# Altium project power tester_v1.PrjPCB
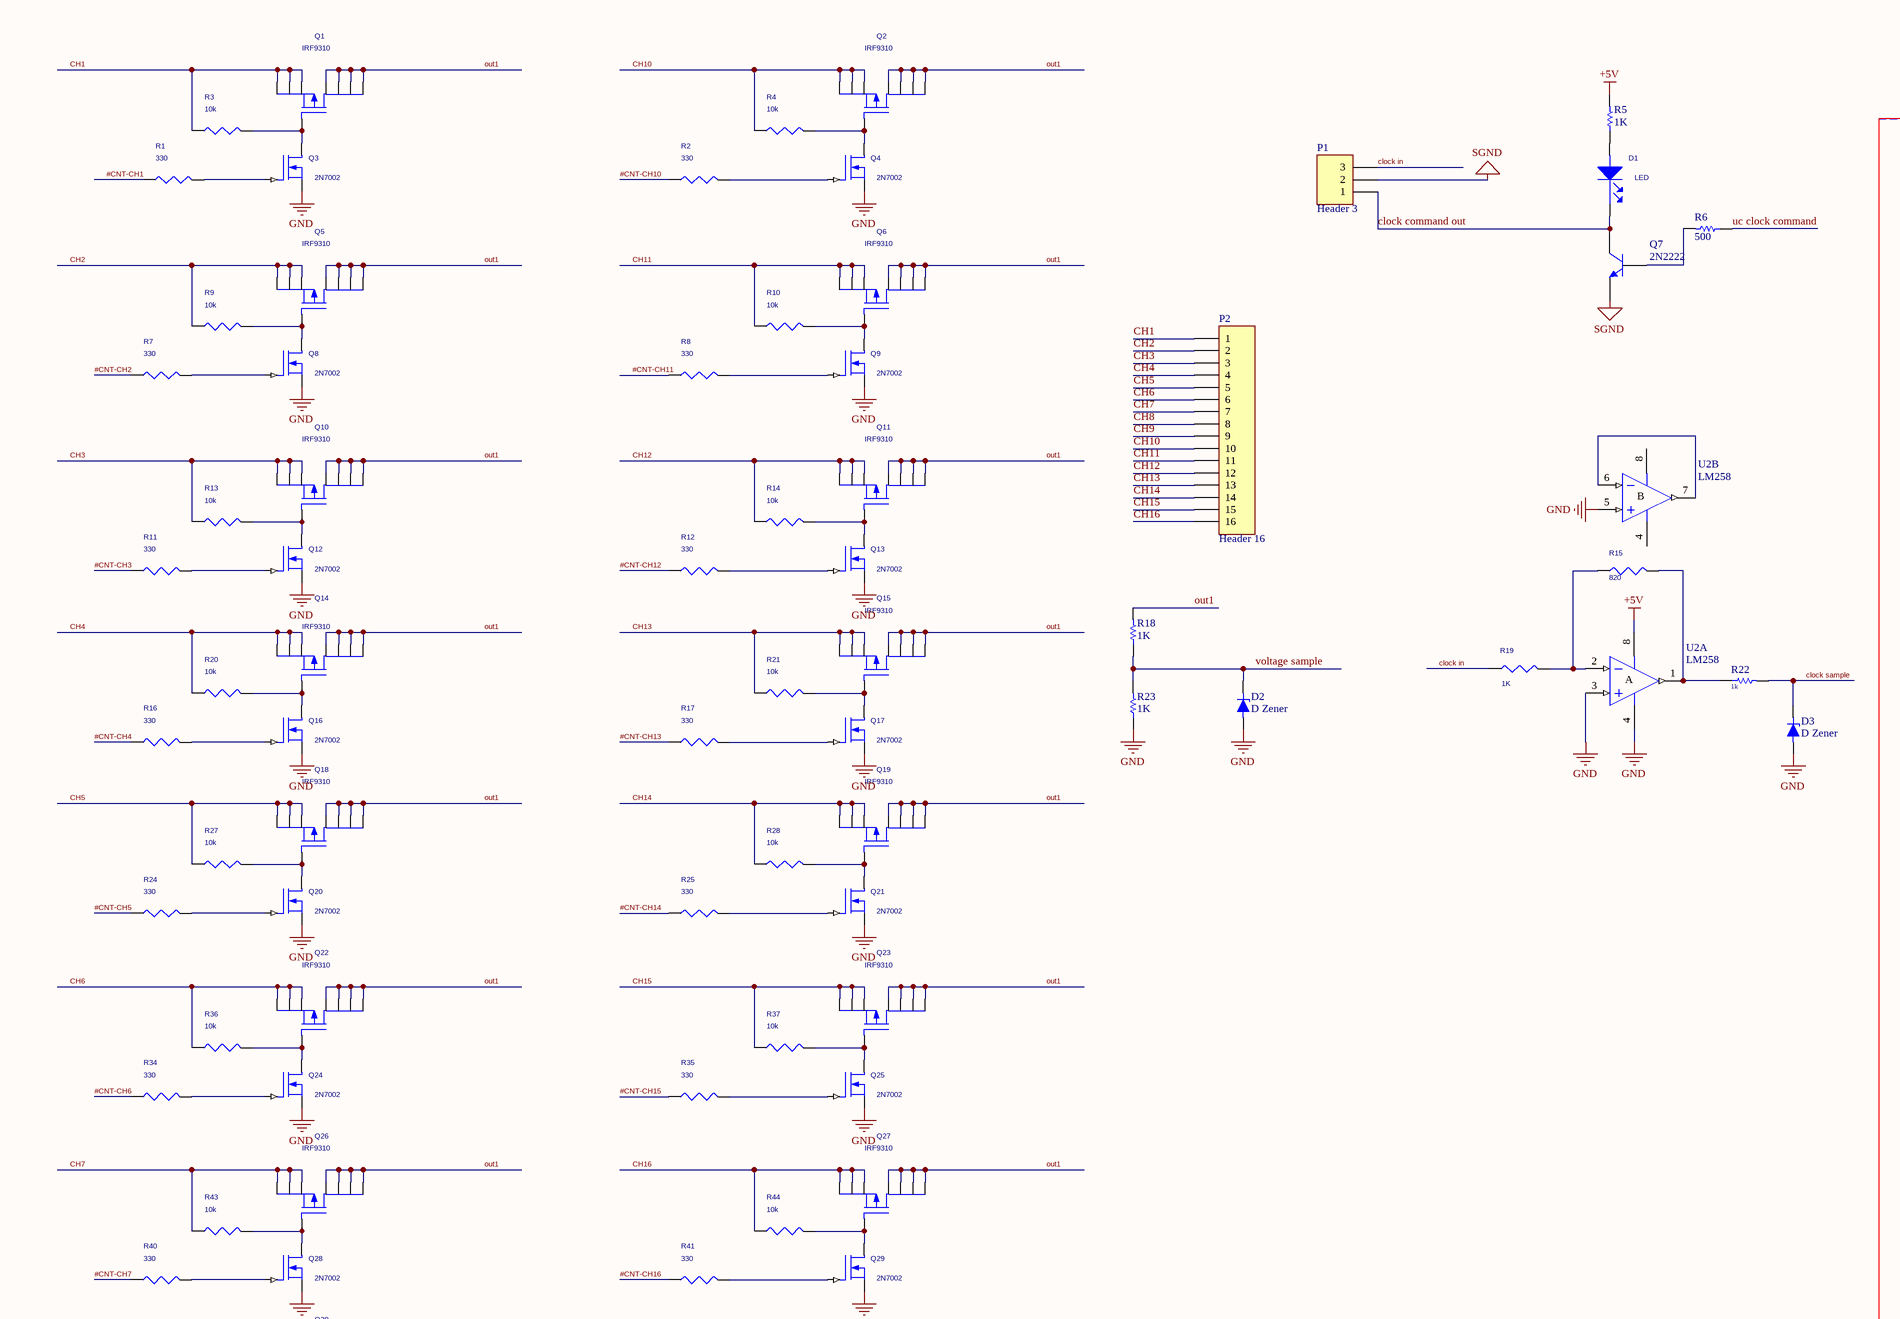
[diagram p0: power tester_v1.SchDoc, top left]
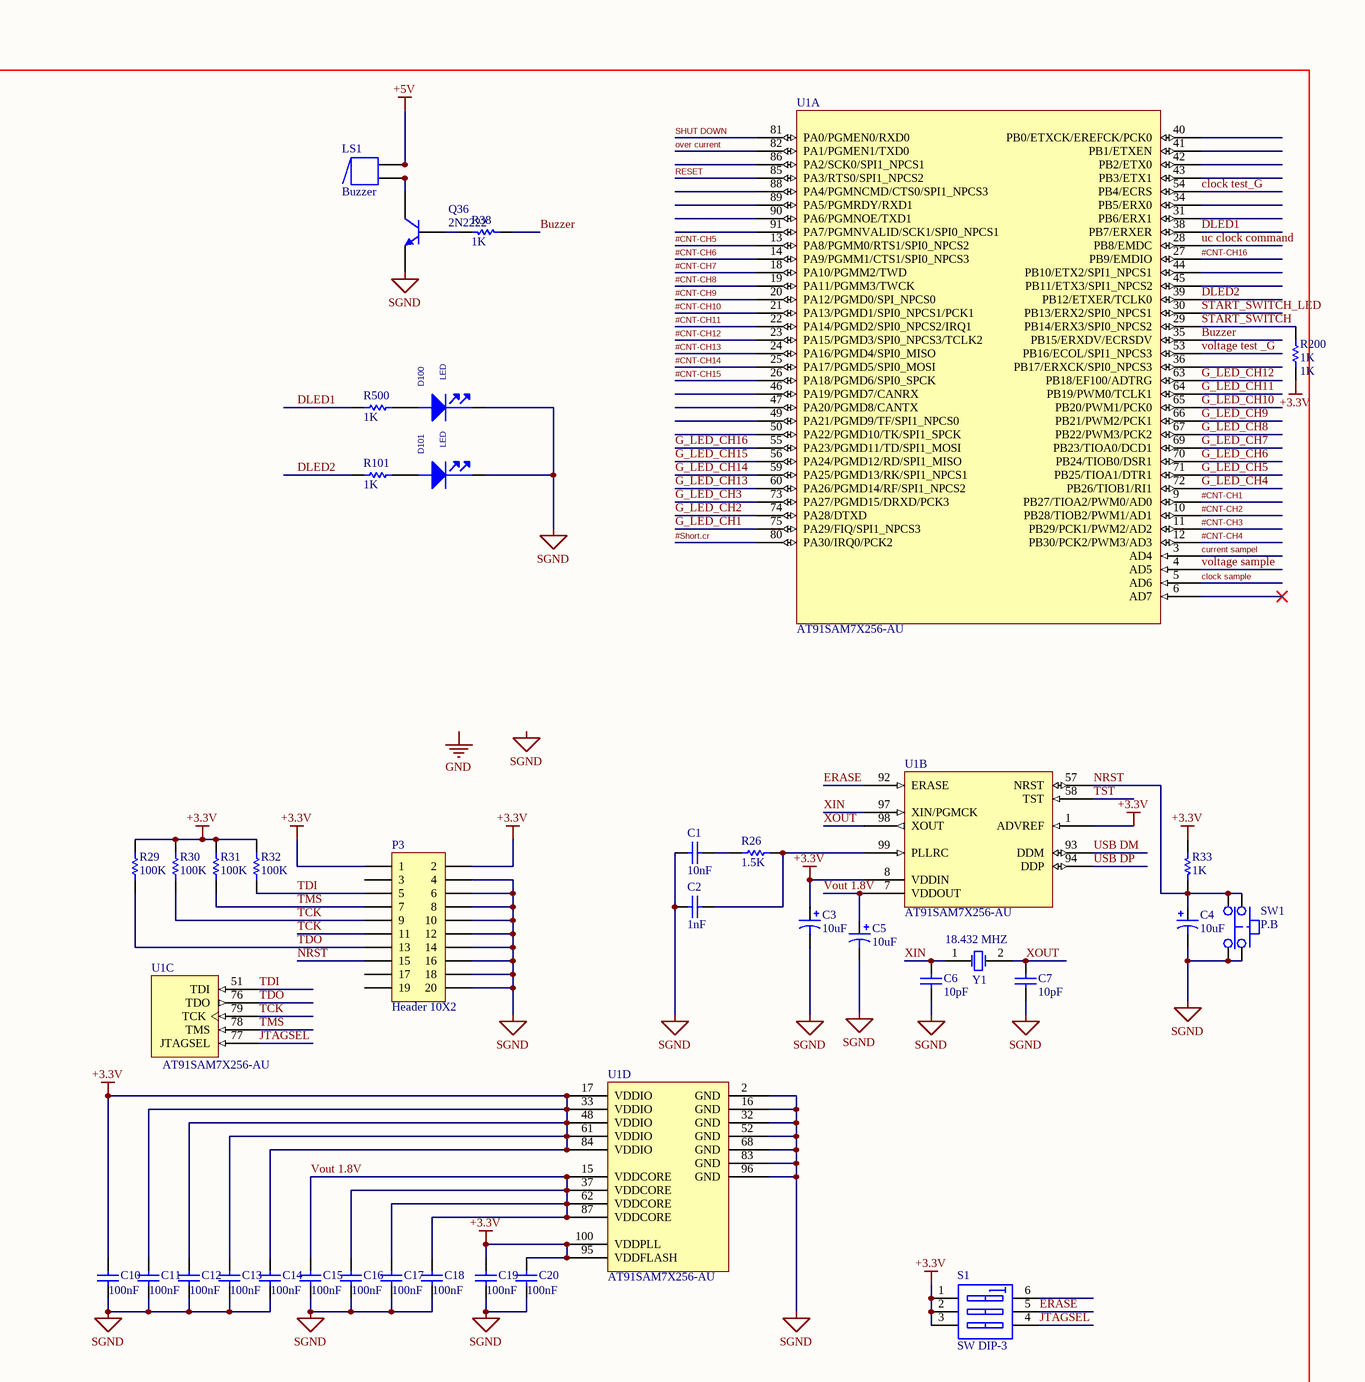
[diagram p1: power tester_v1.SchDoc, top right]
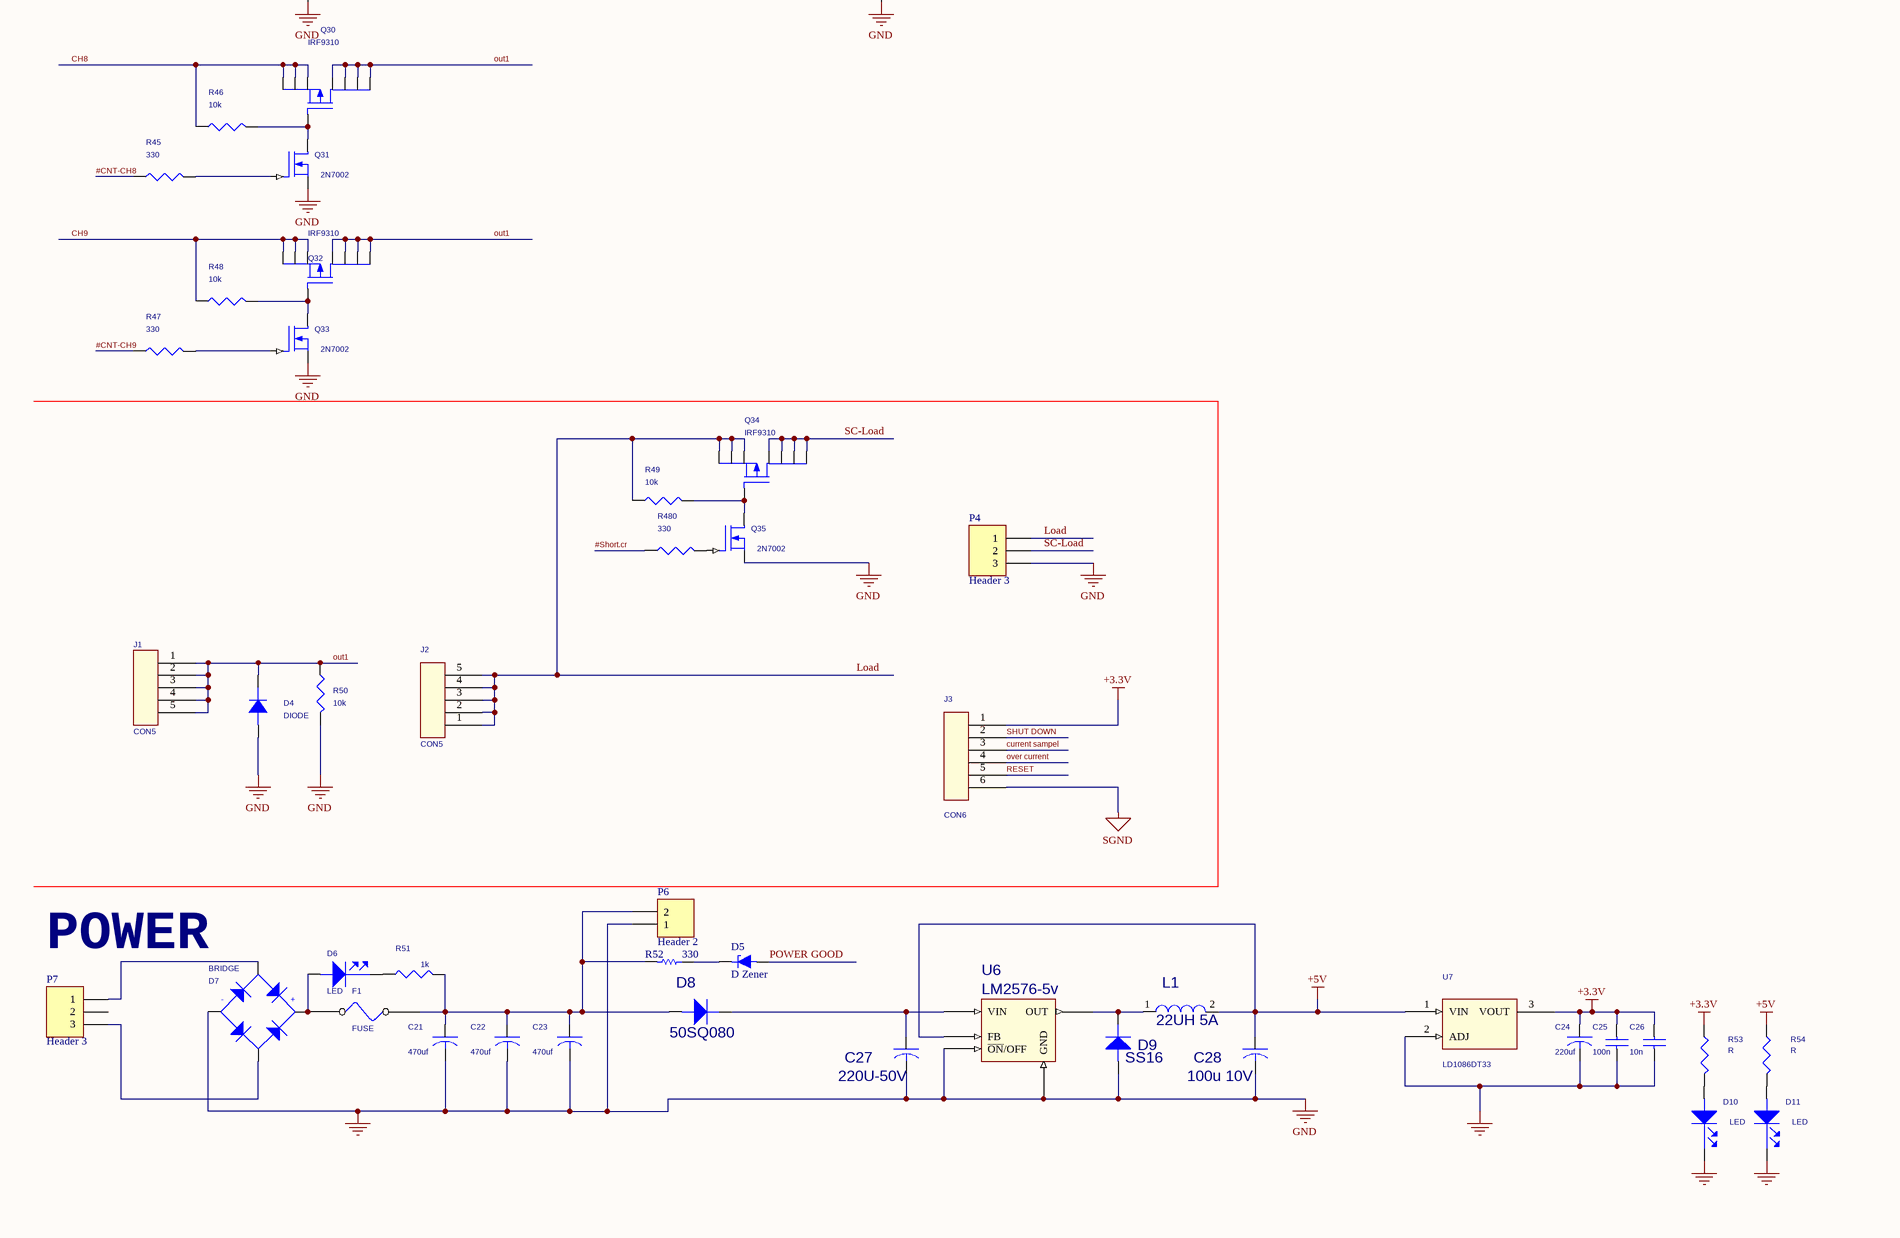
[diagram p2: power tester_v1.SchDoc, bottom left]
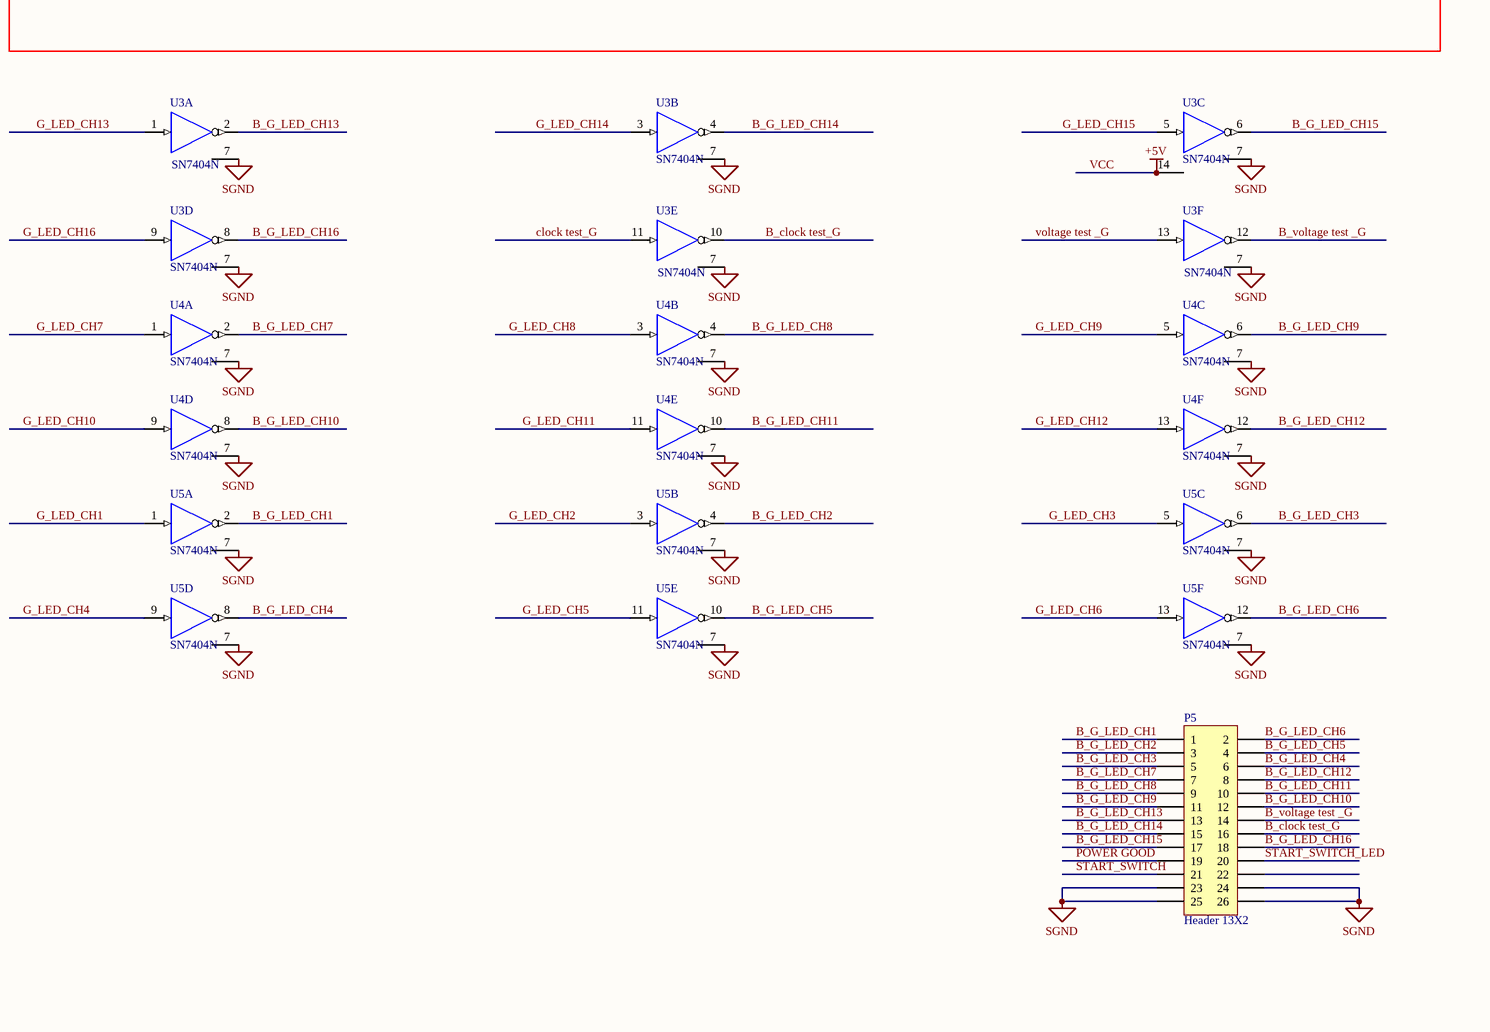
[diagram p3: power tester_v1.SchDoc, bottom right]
1 sheet, 154 parts. Net scope: global (net labels, ports and power ports of the same name join across sheets).
Board file: power tester_v1.PcbDoc

## Sheet power tester_v1.SchDoc
size 660 x 513 mm

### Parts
C1  10nF  [0603BIG]
C2  1nF  [0603BIG]
C3  10uF  [0603BIG]
C4  10uF  [0603BIG]
C5  10uF  [0603BIG]
C6  10pF  [0603BIG]
C7  10pF  [0603BIG]
C10  100nF  [0603BIG]
C11  100nF  [0603BIG]
C12  100nF  [0603BIG]
C13  100nF  [0603BIG]
C14  100nF  [0603BIG]
C15  100nF  [0603BIG]
C16  100nF  [0603BIG]
C17  100nF  [0603BIG]
C18  100nF  [0603BIG]
C19  100nF  [0603BIG]
C20  100nF  [0603BIG]
C21  470uf  [CAP-SMD-HV2]
C22  470uf  [CAP-SMD-HV2]
C23  470uf  [CAP-SMD-HV2]
C24  220uf  [1210-C]
C25  100n  [0603big]
C26  10n  [0603big]
C27  220U-50V  [CAP-SMD-HV2]
C28  100u 10V  [CAP_TANTAL_B]
D1  LED  [0805-d1]
D2  D Zener  [8-1206]
D3  D Zener  [8-1206]
D4  DIODE  [ss14]
D5  D Zener  [8-1206]
D6  LED  [0805-2D]
D7  BRIDGE  [BRG5A]
D8  50SQ080  [SS14]
D9  SS16  [SS14]
D10  LED  [0805-D1]
D11  LED  [0805-d1]
D100  LED  [0805-d1]
D101  LED  [0805-d1]
F1  FUSE  [8-1206]
J1  CON5  [SIP5]
J2  CON5  [SIP5]
J3  CON6  [SIP6]
L1  22UH 5A  [self smd]
LS1  Buzzer  [Buzzer]
P1  Header 3  [mokhaberati3PIN]
P2  Header 16  [wire_connector]
P3  Header 10X2  [IDC20]
P4  Header 3  [PHONIX 3]
P5  Header 13X2  [918526x904]
P6  Header 2  [mokhaberati]
P7  Header 3  [SIP3-155-la]
Q1  IRF9310  [so-8]
Q2  IRF9310  [so-8]
Q3  2N7002  [SOT-23]
Q4  2N7002  [SOT-23]
Q5  IRF9310  [so-8]
Q6  IRF9310  [so-8]
Q7  2N2222  [SOT23_M]
Q8  2N7002  [SOT-23]
Q9  2N7002  [SOT-23]
Q10  IRF9310  [so-8]
Q11  IRF9310  [so-8]
Q12  2N7002  [SOT-23]
Q13  2N7002  [SOT-23]
Q14  IRF9310  [so-8]
Q15  IRF9310  [so-8]
Q16  2N7002  [SOT-23]
Q17  2N7002  [SOT-23]
Q18  IRF9310  [so-8]
Q19  IRF9310  [so-8]
Q20  2N7002  [SOT-23]
Q21  2N7002  [SOT-23]
Q22  IRF9310  [so-8]
Q23  IRF9310  [so-8]
Q24  2N7002  [SOT-23]
Q25  2N7002  [SOT-23]
Q26  IRF9310  [so-8]
Q27  IRF9310  [so-8]
Q28  2N7002  [SOT-23]
Q29  2N7002  [SOT-23]
Q30  IRF9310  [so-8]
Q31  2N7002  [SOT-23]
Q32  IRF9310  [so-8]
Q33  2N7002  [SOT-23]
Q34  IRF9310  [so-8]
Q35  2N7002  [SOT-23]
Q36  2N2222  [SOT23_M]
R1  330  [0603BIG]
R2  330  [0603BIG]
R3  10k  [0603BIG]
R4  10k  [0603BIG]
R5  1K  [0603BIG]
R6  500  [0603BIG]
R7  330  [0603BIG]
R8  330  [0603BIG]
R9  10k  [0603BIG]
R10  10k  [0603BIG]
R11  330  [0603BIG]
R12  330  [0603BIG]
R13  10k  [0603BIG]
R14  10k  [0603BIG]
R15  820  [0603BIG]
R16  330  [0603BIG]
R17  330  [0603BIG]
R18  1K  [0603BIG]
R19  1K  [0603BIG]
R20  10k  [0603BIG]
R21  10k  [0603BIG]
R22  1k  [0603big]
R23  1K  [0603BIG]
R24  330  [0603BIG]
R25  330  [0603BIG]
R26  1.5K  [0603BIG]
R27  10k  [0603BIG]
R28  10k  [0603BIG]
R29  100K  [0603BIG]
R30  100K  [0603BIG]
R31  100K  [0603BIG]
R32  100K  [0603BIG]
R33  1K  [0603BIG]
R34  330  [0603BIG]
R35  330  [0603BIG]
R36  10k  [0603BIG]
R37  10k  [0603BIG]
R38  1K  [0603BIG]
R40  330  [0603BIG]
R41  330  [0603BIG]
R43  10k  [0603BIG]
R44  10k  [0603BIG]
R45  330  [0603BIG]
R46  10k  [0603BIG]
R47  330  [0603BIG]
R48  10k  [0603BIG]
R49  10k  [0603BIG]
R50  10k  [0603BIG]
R51  1k  [0603BIG]
R52  330  [0603BIG]
R53  R  [0603big]
R54  R  [0603big]
R101  1K  [0603BIG]
R200  1K  [0603BIG]
R480  330  [0603BIG]
R500  1K  [0603BIG]
S1  SW DIP-3  [DIP-6]
SW1  P.B  [SW_200]
U1  AT91SAM7X256-AU  [LQFP100]  (parts A,B,C,D of 4)
U2  LM258  [so-8]  (parts A,B of 2)
U3  SN7404N  [D014_N]  (parts A,B,C,D,E,F of 6)
U4  SN7404N  [D014_N]  (parts A,B,C,D,E,F of 6)
U5  SN7404N  [D014_N]  (parts A,B,C,D,E,F of 6)
U6  LM2576-5v  [LM2576-SMD]
U7  LD1086DT33  [7805_SMD]
Y1  18.432 MHZ  [NIRAXTAL-smd]

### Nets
+3.3V: C3.1 C10.2 C11.2 C12.2 C13.2 C14.2 C19.2 C20.2 C24.1 C25.1 C26.1 J3.1 P3.1 P3.2 R29.2 R30.2 R31.2 R32.2 R33.2 R53.1 R200.1 S1.1(A1) S1.2(A2) S1.3(A3) U1.1(ADVREF) U1.8(VDDIN) U1.17(VDDIO) U1.33(VDDIO) U1.48(VDDIO) U1.61(VDDIO) U1.84(VDDIO) U1.95(VDDFLASH) U1.100(VDDPLL) U7.3(VOUT)
GND: C21.2 C22.2 C23.2 C24.2 C25.2 C26.2 C27.2 C28.2 D2.1(A) D3.1(A) D4.A D7.DC- D9.A D10.K D11.K P4.3 P6.1 Q3.3(SOURCE) Q4.3(SOURCE) Q8.3(SOURCE) Q9.3(SOURCE) Q12.3(SOURCE) Q13.3(SOURCE) Q16.3(SOURCE) Q17.3(SOURCE) Q20.3(SOURCE) Q21.3(SOURCE) Q24.3(SOURCE) Q25.3(SOURCE) Q28.3(SOURCE) Q29.3(SOURCE) Q31.3(SOURCE) Q33.3(SOURCE) Q35.3(SOURCE) R23.1 R50.2 U2.3(IN+) U2.4(V-) U2.5(IN+) U6.GND U6.O\N\/OFF(~{ON}/OFF) U7.2(ADJ)
SGND: C1.1 C2.1 C3.2 C4.2 C5.2 C6.1 C7.1 C10.1 C11.1 C12.1 C13.1 C14.1 C15.1 C16.1 C17.1 C18.1 C19.1 C20.1 D100.K D101.K J3.6 P1.2 P3.4 P3.6 P3.8 P3.10 P3.12 P3.14 P3.16 P3.18 P3.20 P5.23 P5.24 P5.25 P5.26 Q7.1(E) Q36.1(E) SW1.1 U1.2(GND) U1.16(GND) U1.32(GND) U1.52(GND) U1.68(GND) U1.83(GND) U1.96(GND) U3.7(GND) U4.7(SGND) U5.7(GND)
VCC: C28.1 L1.2 LS1.1A R5.2 R54.1 U2.8(V+) U3.14(VCC) U4.14(VCC) U5.14(VCC) U6.FB U7.1(VIN)  [also labelled +5V]
#CNT-CH1: R1.1 U1.9(PB27/TIOA2/PWM0/AD0)
#CNT-CH2: R7.1 U1.10(PB28/TIOB2/PWM1/AD1)
#CNT-CH3: R11.1 U1.11(PB29/PCK1/PWM2/AD2)
#CNT-CH4: R16.1 U1.12(PB30/PCK2/PWM3/AD3)
#CNT-CH5: R24.1 U1.13(PA8/PGMM0/RTS1/SPI0_NPCS2)
#CNT-CH6: R34.1 U1.14(PA9/PGMM1/CTS1/SPI0_NPCS3)
#CNT-CH7: R40.1 U1.18(PA10/PGMM2/TWD)
#CNT-CH8: R45.1 U1.19(PA11/PGMM3/TWCK)
#CNT-CH9: R47.1 U1.20(PA12/PGMD0/SPI_NPCS0)
#CNT-CH10: R2.1 U1.21(PA13/PGMD1/SPI0_NPCS1/PCK1)
#CNT-CH11: R8.1 U1.22(PA14/PGMD2/SPI0_NPCS2/IRQ1)
#CNT-CH12: R12.1 U1.23(PA15/PGMD3/SPI0_NPCS3/TCLK2)
#CNT-CH13: R17.1 U1.24(PA16/PGMD4/SPI0_MISO)
#CNT-CH14: R25.1 U1.25(PA17/PGMD5/SPI0_MOSI)
#CNT-CH15: R35.1 U1.26(PA18/PGMD6/SPI0_SPCK)
#CNT-CH16: R41.1 U1.27(PB9/EMDIO)
#Short.cr: R480.1 U1.80(PA30/IRQ0/PCK2)
B_clock test_G: P5.16 U3.10(Y)
B_G_LED_CH1: P5.1 U5.2(Y)
B_G_LED_CH2: P5.3 U5.4(Y)
B_G_LED_CH3: P5.5 U5.6(Y)
B_G_LED_CH4: P5.6 U5.8(Y)
B_G_LED_CH5: P5.4 U5.10(Y)
B_G_LED_CH6: P5.2 U5.12(Y)
B_G_LED_CH7: P5.7 U4.2(Y)
B_G_LED_CH8: P5.9 U4.4(Y)
B_G_LED_CH9: P5.11 U4.6(Y)
B_G_LED_CH10: P5.12 U4.8(Y)
B_G_LED_CH11: P5.10 U4.10(Y)
B_G_LED_CH12: P5.8 U4.12(Y)
B_G_LED_CH13: P5.13 U3.2(Y)
B_G_LED_CH14: P5.15 U3.4(Y)
B_G_LED_CH15: P5.17 U3.6(Y)
B_G_LED_CH16: P5.18 U3.8(Y)
B_voltage test _G: P5.14 U3.12(Y)
Buzzer: R38.1 U1.35(PB15/ERXDV/ECRSDV)
CH1: P2.1 Q1.1(S1) Q1.2(S2) Q1.3(S3) R3.1
CH2: P2.2 Q5.1(S1) Q5.2(S2) Q5.3(S3) R9.1
CH3: P2.3 Q10.1(S1) Q10.2(S2) Q10.3(S3) R13.1
CH4: P2.4 Q14.1(S1) Q14.2(S2) Q14.3(S3) R20.1
CH5: P2.5 Q18.1(S1) Q18.2(S2) Q18.3(S3) R27.1
CH6: P2.6 Q22.1(S1) Q22.2(S2) Q22.3(S3) R36.1
CH7: P2.7 Q26.1(S1) Q26.2(S2) Q26.3(S3) R43.1
CH8: P2.8 Q30.1(S1) Q30.2(S2) Q30.3(S3) R46.1
CH9: P2.9 Q32.1(S1) Q32.2(S2) Q32.3(S3) R48.1
CH10: P2.10 Q2.1(S1) Q2.2(S2) Q2.3(S3) R4.1
CH11: P2.11 Q6.1(S1) Q6.2(S2) Q6.3(S3) R10.1
CH12: P2.12 Q11.1(S1) Q11.2(S2) Q11.3(S3) R14.1
CH13: P2.13 Q15.1(S1) Q15.2(S2) Q15.3(S3) R21.1
CH14: P2.14 Q19.1(S1) Q19.2(S2) Q19.3(S3) R28.1
CH15: P2.15 Q23.1(S1) Q23.2(S2) Q23.3(S3) R37.1
CH16: P2.16 Q27.1(S1) Q27.2(S2) Q27.3(S3) R44.1
clock command out: D1.K P1.1 Q7.3(C)
clock in: P1.3 R19.1
clock sample: D3.2(K) R22.2 U1.5(AD6)
clock test_G: U1.54(PB4/ECRS) U3.11(A)
current sampel: J3.3 U1.3(AD4)
DLED1: R500.2 U1.38(PB7/ERXER)
DLED2: R101.2 U1.39(PB12/ETXER/TCLK0)
ERASE: S1.5(B2) U1.92(ERASE)
G_LED_CH1: U1.75(PA29/FIQ/SPI1_NPCS3) U5.1(A)
G_LED_CH2: U1.74(PA28/DTXD) U5.3(A)
G_LED_CH3: U1.73(PA27/PGMD15/DRXD/PCK3) U5.5(A)
G_LED_CH4: U1.72(PB26/TIOB1/RI1) U5.9(A)
G_LED_CH5: U1.71(PB25/TIOA1/DTR1) U5.11(A)
G_LED_CH6: U1.70(PB24/TIOB0/DSR1) U5.13(A)
G_LED_CH7: U1.69(PB23/TIOA0/DCD1) U4.1(A)
G_LED_CH8: U1.67(PB22/PWM3/PCK2) U4.3(A)
G_LED_CH9: U1.66(PB21/PWM2/PCK1) U4.5(A)
G_LED_CH10: U1.65(PB20/PWM1/PCK0) U4.9(A)
G_LED_CH11: U1.64(PB19/PWM0/TCLK1) U4.11(A)
G_LED_CH12: U1.63(PB18/EF100/ADTRG) U4.13(A)
G_LED_CH13: U1.60(PA26/PGMD14/RF/SPI1_NPCS2) U3.1(A)
G_LED_CH14: U1.59(PA25/PGMD13/RK/SPI1_NPCS1) U3.3(A)
G_LED_CH15: U1.56(PA24/PGMD12/RD/SPI1_MISO) U3.5(A)
G_LED_CH16: U1.55(PA23/PGMD11/TD/SPI1_MOSI) U3.9(A)
JTAGSEL: S1.4(B3) U1.77(JTAGSEL)
Load: J2.1 J2.2 J2.3 J2.4 J2.5 P4.1 Q34.1(S1) Q34.2(S2) Q34.3(S3) R49.1
NRST: C4.1 P3.15 R33.1 SW1.2 U1.57(NRST)
out1: D4.K J1.1 J1.2 J1.3 J1.4 J1.5 Q1.5(D1) Q1.6(D2) Q1.7(D3) Q1.8(D4) Q2.5(D1) Q2.6(D2) Q2.7(D3) Q2.8(D4) Q5.5(D1) Q5.6(D2) Q5.7(D3) Q5.8(D4) Q6.5(D1) Q6.6(D2) Q6.7(D3) Q6.8(D4) Q10.5(D1) Q10.6(D2) Q10.7(D3) Q10.8(D4) Q11.5(D1) Q11.6(D2) Q11.7(D3) Q11.8(D4) Q14.5(D1) Q14.6(D2) Q14.7(D3) Q14.8(D4) Q15.5(D1) Q15.6(D2) Q15.7(D3) Q15.8(D4) Q18.5(D1) Q18.6(D2) Q18.7(D3) Q18.8(D4) Q19.5(D1) Q19.6(D2) Q19.7(D3) Q19.8(D4) Q22.5(D1) Q22.6(D2) Q22.7(D3) Q22.8(D4) Q23.5(D1) Q23.6(D2) Q23.7(D3) Q23.8(D4) Q26.5(D1) Q26.6(D2) Q26.7(D3) Q26.8(D4) Q27.5(D1) Q27.6(D2) Q27.7(D3) Q27.8(D4) Q30.5(D1) Q30.6(D2) Q30.7(D3) Q30.8(D4) Q32.5(D1) Q32.6(D2) Q32.7(D3) Q32.8(D4) R18.2 R50.1
over current: J3.4 U1.82(PA1/PGMEN1/TXD0)
POWER GOOD: D5.1(A) P5.19
RESET: J3.5 U1.85(PA3/RTS0/SPI1_NPCS2)
SC-Load: P4.2 Q34.5(D1) Q34.6(D2) Q34.7(D3) Q34.8(D4)
SHUT DOWN: J3.2 U1.81(PA0/PGMEN0/RXD0)
START_SWITCH: P5.21 R200.2 U1.29(PB14/ERX3/SPI0_NPCS2)
START_SWITCH_LED: P5.20 U1.30(PB13/ERX2/SPI0_NPCS1)
TCK: P3.9 P3.11 R30.1 U1.79(TCK)
TDI: P3.5 R32.1 U1.51(TDI)
TDO: P3.13 R29.1 U1.76(TDO)
TMS: P3.7 R31.1 U1.78(TMS)
TST: U1.58(TST)
uc clock command: R6.1 U1.28(PB8/EMDC)
USB DM: U1.93(DDM)
USB DP: U1.94(DDP)
voltage sample: D2.2(K) R18.1 R23.2 U1.4(AD5)
voltage test _G: U1.53(PB16/ECOL/SPI1_NPCS3) U3.13(A)
Vout 1.8V: C5.1 C15.2 C16.2 C17.2 C18.2 U1.7(VDDOUT) U1.15(VDDCORE) U1.37(VDDCORE) U1.62(VDDCORE) U1.87(VDDCORE)
XIN: C6.2 U1.97(XIN/PGMCK) Y1.1(OSC1)
XOUT: C7.2 U1.98(XOUT) Y1.2(OSC2)
NetC1_2: C1.2 R26.1
NetC2_2: C2.2 R26.2 U1.99(PLLRC)
NetC21_1: C21.1 C22.1 C23.1 D8.A F1.2 P6.2 R51.2 R52.2
NetC27_1: C27.1 D8.K U6.VIN
NetD1_A: D1.A R5.1
NetD5_2: D5.2(K) R52.1
NetD6_A: D6.A D7.DC+ F1.1
NetD6_K: D6.K R51.1
NetD7_AC1: D7.AC1 P7.1
NetD7_AC2: D7.AC2 P7.3
NetD9_K: D9.K L1.1 U6.OUT
NetD10_A: D10.A R53.2
NetD11_A: D11.A R54.2
NetD100_A: D100.A R500.1
NetD101_A: D101.A R101.1
NetLS1_2A: LS1.2A Q36.3(C)
NetQ1_4: Q1.4(G) Q3.2(DRAIN) R3.2
NetQ2_4: Q2.4(G) Q4.2(DRAIN) R4.2
NetQ3_1: Q3.1(GATE) R1.2
NetQ4_1: Q4.1(GATE) R2.2
NetQ5_4: Q5.4(G) Q8.2(DRAIN) R9.2
NetQ6_4: Q6.4(G) Q9.2(DRAIN) R10.2
NetQ7_2: Q7.2(B) R6.2
NetQ8_1: Q8.1(GATE) R7.2
NetQ9_1: Q9.1(GATE) R8.2
NetQ10_4: Q10.4(G) Q12.2(DRAIN) R13.2
NetQ11_4: Q11.4(G) Q13.2(DRAIN) R14.2
NetQ12_1: Q12.1(GATE) R11.2
NetQ13_1: Q13.1(GATE) R12.2
NetQ14_4: Q14.4(G) Q16.2(DRAIN) R20.2
NetQ15_4: Q15.4(G) Q17.2(DRAIN) R21.2
NetQ16_1: Q16.1(GATE) R16.2
NetQ17_1: Q17.1(GATE) R17.2
NetQ18_4: Q18.4(G) Q20.2(DRAIN) R27.2
NetQ19_4: Q19.4(G) Q21.2(DRAIN) R28.2
NetQ20_1: Q20.1(GATE) R24.2
NetQ21_1: Q21.1(GATE) R25.2
NetQ22_4: Q22.4(G) Q24.2(DRAIN) R36.2
NetQ23_4: Q23.4(G) Q25.2(DRAIN) R37.2
NetQ24_1: Q24.1(GATE) R34.2
NetQ25_1: Q25.1(GATE) R35.2
NetQ26_4: Q26.4(G) Q28.2(DRAIN) R43.2
NetQ27_4: Q27.4(G) Q29.2(DRAIN) R44.2
NetQ28_1: Q28.1(GATE) R40.2
NetQ29_1: Q29.1(GATE) R41.2
NetQ30_4: Q30.4(G) Q31.2(DRAIN) R46.2
NetQ31_1: Q31.1(GATE) R45.2
NetQ32_4: Q32.4(G) Q33.2(DRAIN) R48.2
NetQ33_1: Q33.1(GATE) R47.2
NetQ34_4: Q34.4(G) Q35.2(DRAIN) R49.2
NetQ35_1: Q35.1(GATE) R480.2
NetQ36_2: Q36.2(B) R38.2
NetR15_1: R15.1 R19.2 U2.2(IN-)
NetR15_2: R15.2 R22.1 U2.1(OUT)
NetU2_6: U2.6(IN-) U2.7(OUT)

Not connected (* = marked no-connect by the designer): P3 3 17 19; P5 22; P7 2; S1 6(B1); U1 6(AD7)* 31(PB6/ERX1) 34(PB5/ERX0) 36(PB17/ERXCK/SPI0_NPCS3) 40(PB0/ETXCK/EREFCK/PCK0) 41(PB1/ETXEN) 42(PB2/ETX0) 43(PB3/ETX1) 44(PB10/ETX2/SPI1_NPCS1) 45(PB11/ETX3/SPI1_NPCS2) 46(PA19/PGMD7/CANRX) 47(PA20/PGMD8/CANTX) 49(PA21/PGMD9/TF/SPI1_NPCS0) 50(PA22/PGMD10/TK/SPI1_SPCK) 86(PA2/SCK0/SPI1_NPCS1) 88(PA4/PGMNCMD/CTS0/SPI1_NPCS3) 89(PA5/PGMRDY/RXD1) 90(PA6/PGMNOE/TXD1) 91(PA7/PGMNVALID/SCK1/SPI0_NPCS1)

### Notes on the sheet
- POWER
- Labels drawn without touching a wire or pin: GND, SGND

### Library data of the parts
C1 C2 C6 C7 C10-C20 = Cap: Capacitor
C3 C5 = Cap Pol1: 10v
C4 = Cap Pol1: Polarized Capacitor (Radial)
C21-C24 = CAP_Dup1
C25 C26 = C
C27 C28 = CAP
D2 D3 D5 = D Zener: Zener Diode
D4 = DIODE_0
D8 D9 = DIODE
L1 = L: PSpiceTemplate: L^@REFDES %1 %2 ?TOLERANCE¦L^@REFDES¦ @VALUE ?IC/IC=@IC/ ?TOLERANCE¦\n.model l^@REFDES IND L=1 DEV=@TOLERANCE%¦
LS1 = Buzzer: Magnetic Transducer Buzzer
P1 P4 P7 = Header 3: Header, 3-Pin
P2 = Header 16: Header, 16-Pin
P3 = Header 10X2: Header, 10-Pin, Dual row
P5 = Header 13X2: Header, 13-Pin, Dual row
P6 = Header 2: Header, 2-Pin
Q1 Q2 Q5 Q6 Q10 Q11 Q14 Q15 Q18 Q19 Q22 Q23 Q26 Q27 Q30 Q32 Q34 = IRF9310_0
Q3 Q4 Q8 Q9 Q12 Q13 Q16 Q17 Q20 Q21 Q24 Q25 Q28 Q29 Q31 Q33 Q35 = MOSFET N
Q7 Q36 = 2N2222: General Purpose Transistor NPN Silicon
R1-R4 R7-R14 R16 R17 R20 R21 R24 R25 R27 R28 R34-R37 R40 R41 R43-R50 R480 = R_Dup4
R5 R6 R18 R22 R23 R26 R29-R33 R38 R52 R101 R200 R500 = Res1: Resistor
R15 R19 R51 = R
S1 = SW DIP-3: DIP Switch, 3 Position, SPST
SW1 = Push-Button
U1 = AT91SAM7X256-AU: AT91 ARM Thumb-based 32-bit Microcontroller, 256KB Flash, 64KB SRAM, E-MAC, CAN, 100-Pin LQFP, Industrial Grade (-40°C to 85°C), Pb-Free
U2 = OP279GS: Rail-to-Rail High-Output-Current Operational Amplifier
U3-U5 = SN7404N: Hex Inverter
U6 = LM2576/TO_0
U7 = LT1086-12/TO
Y1 = XTAL: Crystal Oscillator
